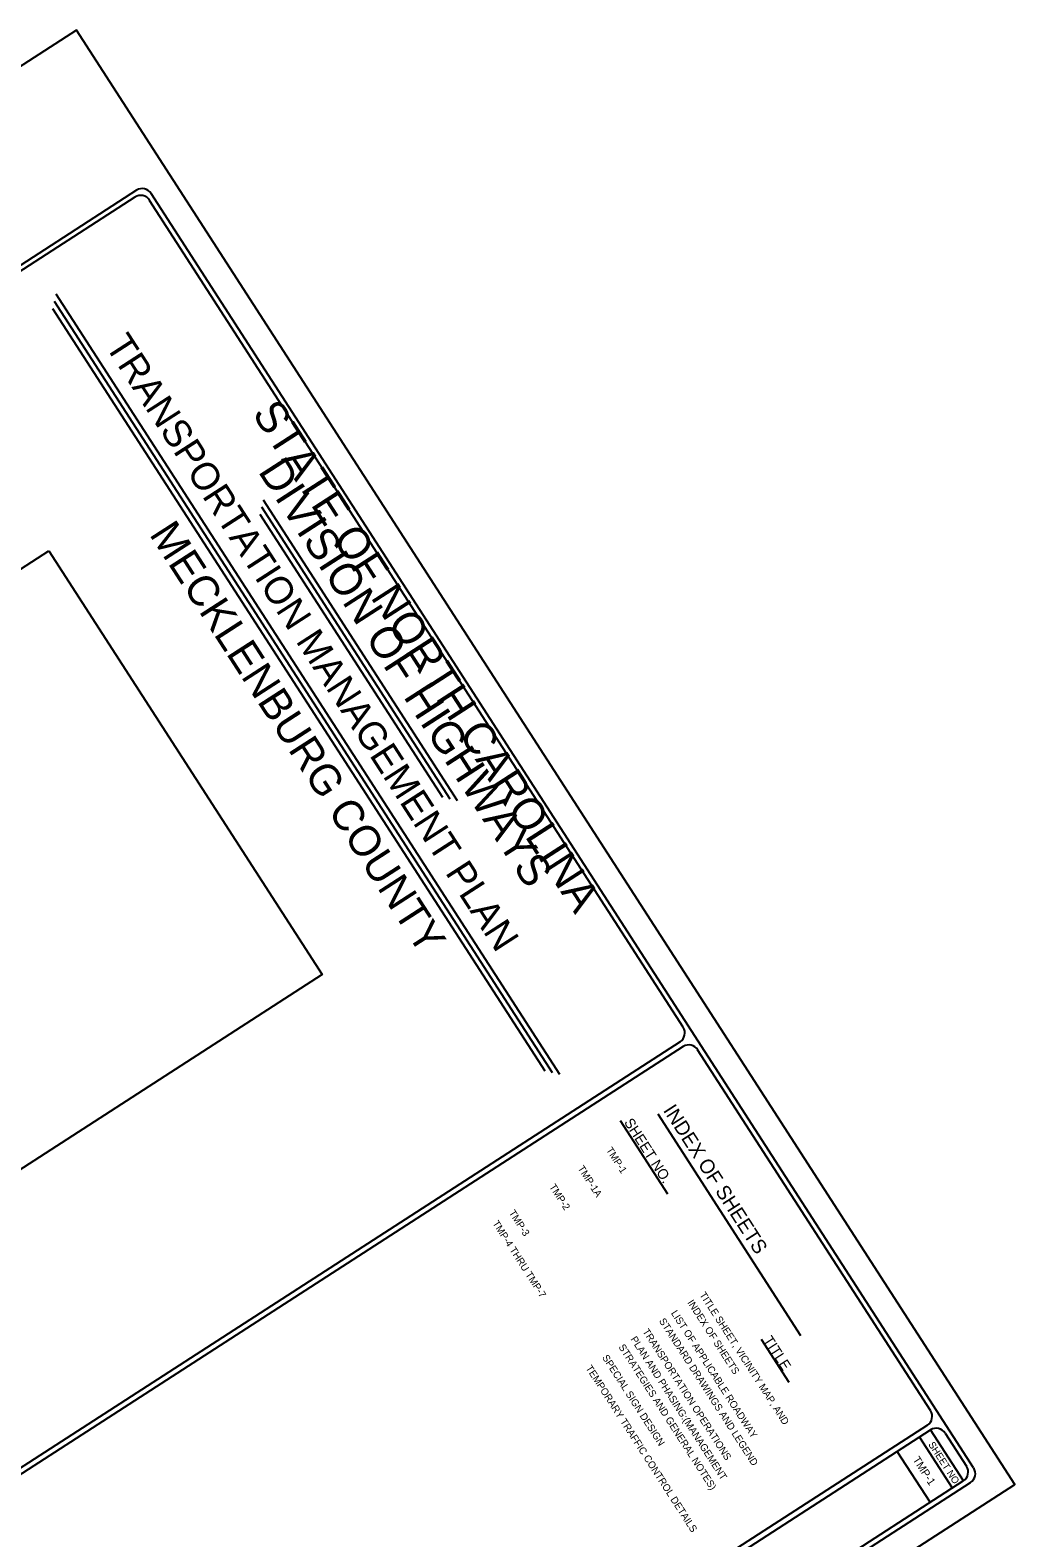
# Model space of a CAD drawing. Extents: x 2160312 to 2162215, y 789569 to 792090.
# Drawn here: x 2161255 to 2162215, y 790620 to 792090 of the extents above; entities that cross this region are included whole.
import ezdxf

# ---------------------------------------------------------------- set-up
doc = ezdxf.new("R2010")
doc.units = 0
for name, color, linetype in [('DEV TITLE SHEET CELL', 7, 'Continuous'), ('Scratch_Level_4', 7, 'Continuous'), ('Sheet Plan CELL', 7, 'Continuous'), ('Sheet Plot Border Outside CELL', 7, 'Continuous')]:
    doc.layers.add(name, color=color, linetype=linetype)

msp = doc.modelspace()

# ---------------------------------------------------------------- linework, layer by layer
at = {"layer": 'DEV TITLE SHEET CELL'}
for p, q in [((2161358.5, 791934), (2160493.6, 791375.7)), ((2162175, 790688), (2161372.7, 791930.9)), ((2161356.8, 791927.2), (2160500.7, 791374.5)), ((2161891.6, 791117.8), (2161371.1, 791924.1)), ((2161279.7, 791832.9), (2161770.9, 791072)), ((2161276.6, 791818.7), (2161756.6, 791075.1)), ((2161278.1, 791825.8), (2161763.8, 791073.6)), ((2161480.3, 791625.1), (2161664, 791340.5)), ((2161481.8, 791632.2), (2161671.1, 791338.9)), ((2161478.8, 791618), (2161656.9, 791342)), ((2161888.6, 791103.6), (2161032.4, 790550.9)), ((2161891.6, 791098.9), (2161035.4, 790546.2)), ((2162132.9, 790744), (2161905.8, 791095.8)), ((2161866.8, 791033.2), (2162006.2, 790817.2)), ((2161830.1, 791026.9), (2161876.5, 790955.1)), ((2161967.6, 790813.5), (2161994.7, 790771.6)), ((2162129.9, 790729.8), (2161273.7, 790177.1)), ((2161276.7, 790172.3), (2162132.9, 790725)), ((2162165, 790675.4), (2162132.9, 790725)), ((2162122.1, 790718.1), (2162154.2, 790668.4)), ((2162147.1, 790722), (2162168.1, 790689.6)), ((2162132.6, 790654.4), (2162100.5, 790704.1)), ((2161307.1, 790115.5), (2162172, 790673.7)), ((2161385.3, 790172), (2162164.9, 790675.3))]:
    msp.add_line(p, q, dxfattribs=at)
for centre, start, end in [((2161364, 791925.3), 32.8434, 122.8434), ((2161362.5, 791918.6), 32.8434, 123.1962), ((2161883, 791112.2), 302.8434, 32.8434), ((2161897.2, 791090.2), 32.8434, 122.8434), ((2162124.3, 790738.4), 302.8434, 32.8434), ((2162138.5, 790716.4), 32.8434, 122.8434), ((2162159.4, 790684), 302.8434, 32.8434), ((2162166.4, 790682.4), 302.8434, 32.8434)]:
    msp.add_arc(centre, 10.3, start, end, dxfattribs=at)
at = {"layer": 'Scratch_Level_4'}
msp.add_lwpolyline([(2161273, 791582.2), (2161539.6, 791169.2), (2161088.8, 790878.2), (2160822.2, 791291.2)], close=True, dxfattribs=at)
at = {"layer": 'Sheet Plan CELL'}
for p, q in [((2162196, 790664.8), (2162196, 790664.8)), ((2162215.2, 790671.9), (2162215.2, 790671.9))]:
    msp.add_line(p, q, dxfattribs=at)
at = {"layer": 'Sheet Plot Border Outside CELL'}
msp.add_lwpolyline([(2160375.6, 791493.5), (2161291, 790075.3), (2162215.2, 790671.9), (2161299.7, 792090.1)], close=True, dxfattribs=at)

# ---------------------------------------------------------------- texts
at = {"layer": 'DEV TITLE SHEET CELL'}
for s, height, rotation, p in [('TRANSPORTATION MANAGEMENT PLAN', 26.998, 302.8434, (2161327.2, 791782.5)), ('STATE OF NORTH CAROLINA', 30.856, 302.8434, (2161470.6, 791716.2)), ('DIVISION OF HIGHWAYS', 30.856, 302.8434, (2161476.4, 791659.8)), ('MECKLENBURG COUNTY', 30, 302.8433, (2161370.3, 791598.5)), ('INDEX OF SHEETS', 13.999, 302.8031, (2161871.7, 791036.7)), ('SHEET NO.', 10, 302.8031, (2161833.6, 791025)), ('TMP-1           ', 7, 302.8031, (2161816.2, 790998)), ('TMP-1A       ', 7, 302.8031, (2161788.5, 790980.1)), ('TMP-2       ', 7, 302.8031, (2161760.8, 790962.2)), ('TMP-4 THRU TMP-7         ', 7, 302.8031, (2161705.3, 790926.5)), ('TMP-3          ', 7, 302.8031, (2161721.3, 790936.8)), ('TITLE SHEET, VICINITY MAP, AND', 7, 302.8031, (2161907.3, 790856.8)), ('LIST OF APPLICABLE ROADWAY', 7, 302.8031, (2161879.5, 790838.9)), ('INDEX OF SHEETS', 7, 302.8031, (2161895.5, 790849.2)), ('STANDARD DRAWINGS AND LEGEND', 7, 302.8031, (2161867.8, 790831.3)), ('PLAN AND PHASING:(MANAGEMENT ', 7, 302.8031, (2161840, 790813.5)), ('TRANSPORTATION OPERATIONS ', 7, 302.8031, (2161851.8, 790821)), ('TITLE', 10, 302.8031, (2161969.4, 790812.6)), ('SPECIAL SIGN DESIGN', 7, 302.8031, (2161812.3, 790795.6)), ('STRATEGIES AND GENERAL NOTES)', 7, 302.8031, (2161828.3, 790805.9)), ('TEMPORARY TRAFFIC CONTROL DETAILS', 7, 302.8031, (2161796.3, 790785.3)), ('SHEET NO.', 6.84, 302.8434, (2162130.5, 790710.8)), ('TMP-1', 7.71, 302.8434, (2162115.2, 790696.1))]:
    msp.add_text(s, height=height, rotation=rotation, dxfattribs=at).set_placement(p)

doc.saveas('drawing.dxf')
